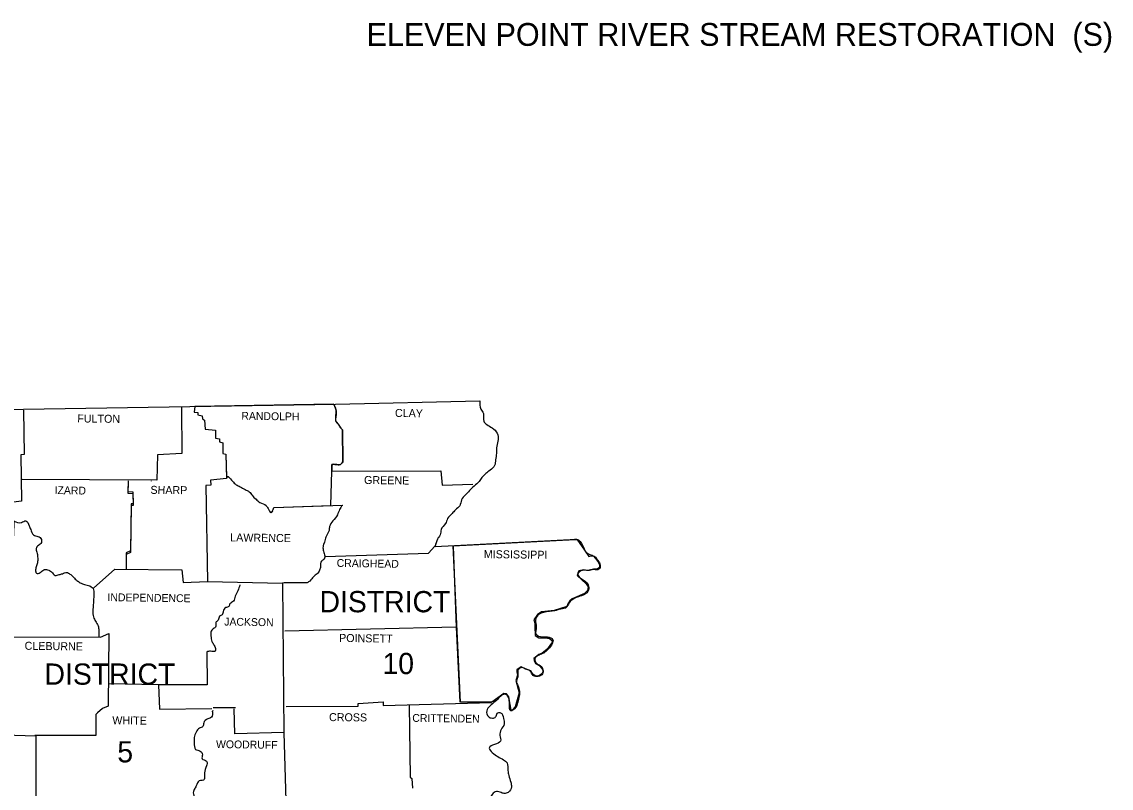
# Model space of a CAD drawing. Extents: x -549 to 3324, y -742 to 2142.
# Drawn here: x 2752 to 3324, y 1662 to 2065 of the extents above; entities that cross this region are included whole.
import ezdxf

# ---------------------------------------------------------------- set-up
doc = ezdxf.new("R2010")
doc.units = 0
for name, color, linetype in [('1', 7, 'Continuous'), ('2', 7, 'Continuous'), ('3', 7, 'Continuous'), ('R_Border', 7, 'Continuous'), ('S_MISC_BOUNDARY', 7, 'Continuous')]:
    doc.layers.add(name, color=color, linetype=linetype)

msp = doc.modelspace()

# ---------------------------------------------------------------- linework, layer by layer
at = {"layer": '1'}
for p, q in [((2915.77, 1863.94), (2842.91, 1862.81)), ((2920.62, 1833.62), (2920.52, 1850.55)), ((2914.85, 1832.35), (2914.85, 1828.73)), ((2914.85, 1828.73), (2914.85, 1832.35)), ((2914.33, 1810.8), (2914.85, 1828.73)), ((2859.45, 1825.76), (2860.55, 1825.8)), ((2884.42, 1809.75), (2914.33, 1810.8)), ((2914.16, 1810.72), (2914.34, 1810.9)), ((2882.86, 1807.1), (2883.8, 1808.03)), ((2969.15, 1789.3), (2970.32, 1792.92)), ((2969.44, 1790.48), (2970.62, 1793.31)), ((2978.62, 1789.66), (3042.98, 1792.83)), ((3042.98, 1792.83), (3043.54, 1792.85)), ((3043.54, 1792.85), (3043.99, 1792.54)), ((3043.99, 1792.54), (3045.23, 1790.75)), ((2982.43, 1707.4), (2978.62, 1789.66)), ((3045.23, 1790.75), (3047.58, 1787.37)), ((3047.58, 1787.37), (3049.93, 1783.98)), ((3049.93, 1783.98), (3051.1, 1784.31)), ((3051.1, 1784.31), (3052.3, 1784.1)), ((3052.3, 1784.1), (3053.39, 1783)), ((3053.39, 1783), (3054.61, 1781.37)), ((3054.61, 1781.37), (3055.54, 1779.56)), ((3044.31, 1775.81), (3043.85, 1774.02)), ((3044.71, 1776.36), (3044.31, 1775.81)), ((3047.22, 1776.92), (3044.71, 1776.36)), ((3049.3, 1776.68), (3047.22, 1776.92)), ((3052.45, 1777.3), (3049.3, 1776.68)), ((3054.34, 1777.33), (3052.45, 1777.3)), ((3055.55, 1778.19), (3054.34, 1777.33)), ((3055.54, 1779.56), (3055.55, 1778.19)), ((3043.85, 1774.02), (3048.55, 1769.65)), ((3048.55, 1769.65), (3049.63, 1768.04)), ((3047.61, 1764.55), (3041.23, 1761.72)), ((3049.21, 1766.16), (3047.61, 1764.55)), ((3049.63, 1768.04), (3049.21, 1766.16)), ((3038.33, 1757.73), (3031.69, 1755.63)), ((3038.82, 1759.16), (3038.33, 1757.73)), ((3039.97, 1760.65), (3038.82, 1759.16)), ((3041.23, 1761.72), (3039.97, 1760.65)), ((3022.89, 1753.52), (3020.94, 1750.76)), ((3025.12, 1754.93), (3022.89, 1753.52)), ((3031.69, 1755.63), (3025.12, 1754.93)), ((3020.94, 1750.76), (3021.55, 1748.97)), ((3021.55, 1748.97), (3021.55, 1747.09)), ((3021.55, 1747.09), (3021.73, 1742.42)), ((3021.73, 1742.42), (3023.7, 1741.24)), ((3023.7, 1741.24), (3025.99, 1741.17)), ((3025.99, 1741.17), (3028.28, 1741.1)), ((3028.28, 1741.1), (3029.12, 1741.07)), ((3029.12, 1741.07), (3030.19, 1740.26)), ((3028.03, 1735.21), (3025.4, 1733.21)), ((3030.84, 1739.21), (3028.03, 1735.21)), ((3030.19, 1740.26), (3030.84, 1739.21)), ((3023.67, 1732.48), (3021.04, 1730.35)), ((3021.04, 1730.35), (3021.13, 1729.35)), ((3021.13, 1729.35), (3021.94, 1727.82)), ((3025.4, 1733.21), (3023.67, 1732.48)), ((3014.34, 1725.93), (3012.02, 1724.44)), ((3012.02, 1724.44), (3012.13, 1723.3)), ((3012.13, 1723.3), (3012.47, 1721.63)), ((3016.57, 1725.02), (3014.34, 1725.93)), ((3019.46, 1723.84), (3016.57, 1725.02)), ((3020.41, 1722.09), (3019.46, 1723.84)), ((3021.94, 1727.82), (3023.87, 1726.75)), ((3023.87, 1726.75), (3025.35, 1724.96)), ((3025.86, 1723.55), (3025.28, 1722.29)), ((3025.35, 1724.96), (3025.86, 1723.55)), ((3012.47, 1721.63), (3011.49, 1718.8)), ((3011.49, 1718.8), (3013.22, 1712.29)), ((3022.15, 1721.11), (3020.41, 1722.09)), ((3023.55, 1721.16), (3022.15, 1721.11)), ((3025.28, 1722.29), (3023.55, 1721.16)), ((3005.26, 1711.99), (2998.98, 1707.52)), ((3006.68, 1711.89), (3005.26, 1711.99)), ((3007.96, 1710.3), (3006.68, 1711.89)), ((3013.22, 1712.29), (3011.16, 1704.98)), ((2998.98, 1707.52), (2982.43, 1707.4)), ((3009.18, 1703.2), (3007.96, 1710.3)), ((2852.52, 1704.57), (2864.17, 1704.57)), ((3009.73, 1703.39), (3009.18, 1703.2)), ((3011.16, 1704.98), (3009.73, 1703.39))]:
    msp.add_line(p, q, dxfattribs=at)
for points in [[(2455.88, 1861.21), (2614.09, 1861.12), (2752.92, 1861.41), (2916.71, 1863.95), (2992.63, 1865.72)], [(2752.92, 1860.82), (2753.12, 1837.54), (2751.45, 1837.44), (2751.75, 1813.08), (2744.9, 1812.1), (2745.49, 1805.54), (2747.83, 1802.51), (2747.64, 1794.78), (2734.33, 1794.29), (2733.84, 1782.36), (2721.71, 1781.96), (2721.12, 1767.48), (2721.81, 1766.31), (2722.1, 1743.22), (2743.04, 1741.85), (2742.75, 1690.29), (2759.38, 1689.8), (2759.38, 1637.36), (2746.27, 1636.38), (2745.29, 1624.83), (2723.28, 1624.73)], [(2835.79, 1862.29), (2835.99, 1838.03), (2823.27, 1837.34), (2822.88, 1824.04), (2752.14, 1824.43)], [(2842.91, 1862.81), (2842.54, 1859.84), (2844.5, 1859.55), (2844.4, 1858.38), (2846.65, 1857.89), (2846.85, 1856.32), (2847.93, 1855.64), (2848.22, 1850.94), (2853.8, 1850.35), (2853.8, 1846.15), (2855.85, 1845.85), (2855.85, 1844.19), (2857.61, 1843.7), (2857.51, 1838.03), (2859.08, 1837.73), (2859.47, 1824.92), (2851.15, 1824.13), (2851.25, 1821.39), (2848.71, 1821.3), (2849.59, 1770.81), (2889.02, 1769.93), (2889.7, 1691.46), (2863.97, 1690.78), (2863.48, 1703.98)], [(2842.91, 1862.81), (2842.54, 1859.84), (2844.5, 1859.55), (2844.4, 1858.38), (2846.65, 1857.89), (2846.85, 1856.32), (2847.93, 1855.64), (2848.22, 1850.94), (2853.8, 1850.35), (2853.8, 1846.15), (2855.85, 1845.85), (2855.85, 1844.19), (2857.61, 1843.7), (2857.51, 1838.03), (2859.08, 1837.73), (2859.45, 1825.76)], [(2920.52, 1850.55), (2920.62, 1833.62)], [(2914.33, 1810.8), (2914.85, 1828.73), (2914.85, 1828.73), (2972.09, 1829.03), (2972.87, 1821.39), (2989.01, 1821.98)], [(2807.81, 1823.74), (2807.62, 1818.07), (2810.35, 1817.87), (2810.45, 1811.61), (2809.47, 1811.61), (2809.08, 1786.95), (2806.83, 1785.98), (2806.83, 1777.76)], [(2807.81, 1822.86), (2807.62, 1817.19), (2810.35, 1816.99), (2810.45, 1810.73), (2809.47, 1810.73), (2809.08, 1786.07), (2806.83, 1785.09), (2806.83, 1776.88)], [(2820.04, 1823.55), (2820.14, 1823.64)], [(2884.42, 1809.75), (2920.72, 1811.02)], [(2969.15, 1789.3), (3043.41, 1793.12)], [(2911.42, 1783.92), (2965.73, 1785.68), (2968.95, 1789.4)], [(2978.54, 1789.2), (2980.21, 1746.84), (2982.16, 1707.41)], [(2789.61, 1767.29), (2800.77, 1777.37), (2835.99, 1776.88), (2836.67, 1770.32), (2849.49, 1770.81)], [(2901.84, 1770.13), (2889.9, 1770.13), (2889.02, 1769.93)], [(2980.21, 1746.84), (2890.1, 1744.78)], [(2743.04, 1741.85), (2793.33, 1741.56), (2797.64, 1743.61), (2797.34, 1705.35), (2794.41, 1704.08), (2791.77, 1701.83), (2790.88, 1700.95), (2790.79, 1689.99), (2758.79, 1689.99)], [(2849.1, 1733.83), (2849.3, 1716.61), (2823.86, 1716.51), (2797.73, 1717)], [(2823.86, 1716.51), (2824.25, 1703.69), (2851.74, 1704.18)], [(2890.88, 1705.16), (2928.64, 1705.35), (2928.74, 1706.72), (2941.85, 1707.7), (2941.85, 1705.65), (2998.8, 1707.21)], [(2852.52, 1702.91), (2852.04, 1702.81)], [(2955.55, 1705.65), (2956.04, 1667.98), (2956.92, 1667.39), (2957.21, 1662.3)], [(2889.7, 1691.46), (2891.17, 1637.84), (2867.89, 1637.75), (2867.79, 1635.59), (2861.04, 1635.2), (2860.45, 1624.05), (2852.23, 1624.05)]]:
    msp.add_lwpolyline(points, dxfattribs=at)
for points in [[(2915.76, 1863.94), (2917.1, 1860.24), (2917, 1857.59), (2917, 1855.15), (2918.27, 1853.49), (2919.55, 1851.43), (2920.52, 1850.55)], [(2920.52, 1850.55), (2920.25, 1850.75), (2920, 1850.96), (2919.76, 1851.18), (2919.55, 1851.43), (2919.37, 1851.68), (2919.2, 1851.93), (2918.89, 1852.45), (2918.59, 1852.98), (2918.27, 1853.49), (2918.11, 1853.69), (2917.93, 1853.89), (2917.54, 1854.27), (2917.2, 1854.68), (2917, 1855.15), (2916.99, 1855.22), (2916.98, 1855.3), (2916.96, 1855.45), (2916.93, 1855.76), (2916.94, 1856.37), (2916.99, 1857.29), (2917, 1857.59), (2917.02, 1858.26), (2917.06, 1858.92), (2917.08, 1859.58), (2917.1, 1860.24), (2917.09, 1860.74), (2917.04, 1861.24), (2916.81, 1862.25), (2916.11, 1863.58), (2915.77, 1863.94)], [(2992.63, 1865.72), (2993.12, 1861.41), (2994.49, 1859.16), (2994.69, 1855.05), (2996.35, 1853.29), (2999.19, 1851.53), (3001.73, 1848.69), (3002.32, 1845.36), (3001.54, 1841.94), (3001.34, 1838.12), (3000.95, 1834.8), (3000.36, 1831.76), (2998.01, 1829.32), (2995.76, 1827.56), (2993.71, 1825.5), (2992.24, 1823.35), (2989.7, 1821), (2987.15, 1818.56), (2985.1, 1816.4), (2983.04, 1813.66), (2982.07, 1810.63), (2979.82, 1808.48), (2978.05, 1806.52), (2975.71, 1803.88), (2974.53, 1801.24), (2972.28, 1798.21), (2971.79, 1795.27), (2970.32, 1792.92), (2970.23, 1792.53)], [(2920.62, 1833.62), (2919.35, 1832.35), (2916.9, 1832.35), (2914.85, 1832.35)], [(2914.85, 1832.35), (2916.9, 1832.35), (2919.35, 1832.35), (2920.62, 1833.62)], [(2860.55, 1825.8), (2862.7, 1823.55), (2864.56, 1821.69), (2866.71, 1820.61), (2869.26, 1819.14), (2871.51, 1817.97), (2872.97, 1816.11), (2875.03, 1814.06), (2877.08, 1812.39), (2880.31, 1810.83), (2881.39, 1809.16), (2882.85, 1807.11), (2884.42, 1809.75)], [(2860.55, 1825.8), (2862.7, 1823.55), (2864.56, 1821.69), (2866.71, 1820.61), (2869.26, 1819.14), (2871.51, 1817.97), (2872.97, 1816.11), (2875.03, 1814.06), (2877.08, 1812.39), (2880.31, 1810.83), (2881.39, 1809.16), (2882.85, 1807.11), (2884.42, 1809.75)], [(2920.43, 1810.92), (2918.96, 1808.58), (2917.78, 1805.84), (2915.44, 1802.71), (2913.67, 1799.67), (2913.38, 1797.62), (2912.01, 1794.88), (2911.23, 1792.14), (2910.35, 1789.79), (2910.35, 1787.35), (2911.03, 1784.9), (2910.84, 1782.65), (2909.37, 1781.57), (2908.98, 1778.74), (2908.39, 1776.78), (2907.12, 1774.82), (2905.26, 1773.35), (2903.3, 1771.1), (2901.84, 1770.13)], [(2747.83, 1802.51), (2751.75, 1801.83), (2754.1, 1802.71), (2755.76, 1800.16), (2756.64, 1798.21), (2758.11, 1795.37), (2760.46, 1794.49), (2762.22, 1792.92), (2762.22, 1791.26), (2760.65, 1789.69), (2759.48, 1788.13), (2759.87, 1786.27), (2760.26, 1783.72), (2760.26, 1781.28), (2759.67, 1779.03), (2759.18, 1776.97), (2759.67, 1775.21), (2761.53, 1775.51), (2763.49, 1776.97), (2765.54, 1776.97), (2767.5, 1775.9), (2769.56, 1774.04), (2771.61, 1774.43), (2773.27, 1774.92), (2775.62, 1775.6), (2777.28, 1774.72), (2778.75, 1773.55), (2780.51, 1771.69), (2782.18, 1770.52), (2784.33, 1769.44), (2786.97, 1768.76), (2789.42, 1767.09), (2789.81, 1764.25), (2789.71, 1761.81), (2789.51, 1758.78), (2789.32, 1755.45), (2789.61, 1752.22), (2790.69, 1750.07), (2792.06, 1747.52), (2792.45, 1745.18), (2792.35, 1741.46)], [(3042.34, 1793.02), (3043.41, 1793.12), (3046.74, 1789.6), (3048.21, 1786.66), (3050.36, 1785), (3052.8, 1784.12), (3054.66, 1781.87), (3055.94, 1779.42), (3055.25, 1777.27), (3052.51, 1777.07), (3049.48, 1776.58), (3046.54, 1776.68), (3044.19, 1774.72), (3046.35, 1772.08), (3049.18, 1769.64), (3049.97, 1766.99), (3048.4, 1764.45), (3045.27, 1763.08), (3042.24, 1761.91), (3039.5, 1759.56), (3038.23, 1757.31), (3035.19, 1756.33), (3032.06, 1755.45), (3029.32, 1755.16), (3026.19, 1754.57), (3023.16, 1753.1), (3021.89, 1750.56), (3022.28, 1746.94), (3022.18, 1743.12), (3025.41, 1741.85), (3028.25, 1741.75), (3030.99, 1740.28), (3030.69, 1738.13), (3028.64, 1735.39), (3026.19, 1733.24), (3023.75, 1732.16), (3021.5, 1730.11), (3022.28, 1728.05), (3024.33, 1726.68), (3025.8, 1724.43), (3025.6, 1722.38), (3023.26, 1720.91), (3020.71, 1721.5), (3018.85, 1723.94), (3016.7, 1724.73), (3014.84, 1725.61), (3012.69, 1724.34), (3012.69, 1721.5), (3011.91, 1718.47), (3012.59, 1716.21), (3013.47, 1713.08), (3013.37, 1710.74), (3012.59, 1707.41), (3010.93, 1703.98), (3008.97, 1702.91), (3008.19, 1706.63), (3007.8, 1709.66), (3006.62, 1711.42), (3005.06, 1711.52), (3003, 1710.05), (3000.75, 1707.8), (2997.92, 1705.35), (2996.25, 1702.91), (2997.13, 1699.88), (2999.29, 1699.09), (3000.95, 1699.68), (3001.83, 1701.64), (3003.49, 1701.93), (3005.06, 1698.9)], [(2866.61, 1769.05), (2865.44, 1766.02), (2864.07, 1763.08), (2863.19, 1760.54), (2861.33, 1759.07), (2860.74, 1757.7), (2859.08, 1757.11), (2857.81, 1755.16), (2857.22, 1753.39), (2855.85, 1752.61), (2855.17, 1750.46), (2853.89, 1749.29), (2853.99, 1747.33), (2852.52, 1745.96), (2851.35, 1744.39), (2851.35, 1742.24), (2851.84, 1739.4), (2852.82, 1737.74), (2853.7, 1735.59), (2853.6, 1734.22), (2851.15, 1734.22), (2849.1, 1733.83)], [(2852.04, 1702.81), (2851.55, 1699.58), (2849.69, 1698.7), (2847.53, 1696.55), (2847.05, 1694.59), (2845.28, 1693.81), (2843.62, 1691.75), (2842.54, 1688.92), (2842.54, 1685.98), (2843.23, 1682.66), (2845.68, 1681.77), (2846.85, 1679.82), (2846.65, 1677.76), (2849, 1676.39), (2849.39, 1675.22), (2849, 1673.95), (2847.93, 1670.33), (2848.02, 1667.88), (2847.83, 1666.81), (2845.19, 1666.12), (2843.62, 1663.48), (2842.54, 1661.62), (2842.15, 1659.17), (2842.45, 1657.41), (2841.66, 1656.04), (2841.37, 1653.99), (2840.39, 1652.23), (2839.51, 1650.56), (2840.49, 1648.61), (2840.2, 1647.24), (2839.61, 1645.08), (2840.1, 1644.4)], [(3005.06, 1698.9), (3005.45, 1696.06), (3003.79, 1693.03), (3003.2, 1689.99), (3003.49, 1686.96), (3000.36, 1685.3), (2997.62, 1683.34), (2999.19, 1680.99), (3002.12, 1678.84), (3005.06, 1677.18), (3006.92, 1675.51), (3007.41, 1671.5), (3007.9, 1668.96), (3008.87, 1665.44), (3009.27, 1662.99), (3007.5, 1660.05), (3005.45, 1659.47), (3003.3, 1660.15), (3000.75, 1660.35), (2998.7, 1658.39), (2997.23, 1655.65), (2995.76, 1652.91), (2994.69, 1650.56), (2993.61, 1648.02), (2991.46, 1645.08), (2988.82, 1644.6), (2985.69, 1643.81), (2983.83, 1641.66), (2984.12, 1638.04), (2985.88, 1635.59), (2987.25, 1632.56), (2988.23, 1629.92), (2987.74, 1626.59), (2986.37, 1624.15), (2984.61, 1622.68), (2983.83, 1619.55), (2982.55, 1617.2), (2981.38, 1616.42), (2979.03, 1616.61), (2976.49, 1617.1), (2974.34, 1616.91), (2972.28, 1615.83), (2970.23, 1616.52), (2968.07, 1618.86), (2966.31, 1620.62), (2964.36, 1621.31), (2962.3, 1620.23), (2961.91, 1617), (2962.89, 1613.68), (2963.77, 1609.18), (2962.89, 1606.44), (2962.6, 1601.94)]]:
    msp.add_spline(points, degree=3, dxfattribs=at)
at = {"layer": 'S_MISC_BOUNDARY'}
msp.add_line((2860.55, 1825.8), (2859.45, 1825.76), dxfattribs=at)

# ---------------------------------------------------------------- texts
at = {"layer": '2'}
for s, height, rotation, p in [('CLAY', 4.206, 359.2258, (2948.02, 1857.3)), ('FULTON', 4.206, 359.4996, (2781.1, 1854.37)), ('RANDOLPH', 4.109, 359.2583, (2867.3, 1855.83)), ('GREENE', 4.207, 359.2361, (2931.78, 1822.08)), ('IZARD', 4.108, 358.9258, (2769.16, 1816.8)), ('SHARP', 4.206, 359.3905, (2819.55, 1816.89)), ('LAWRENCE', 4.207, 359.2678, (2861.45, 1791.91)), ('MISSISSIPPI', 4.2062, 359.3097, (2994.69, 1783.14)), ('CRAIGHEAD', 4.109, 359.1159, (2917.39, 1778.54)), ('INDEPENDENCE', 4.1081, 359.2187, (2796.95, 1760.54)), ('JACKSON', 4.108, 359.1352, (2858.3, 1747.72)), ('POINSETT', 4.206, 359.1987, (2918.66, 1739.11)), ('CLEBURNE', 4.206, 359.2535, (2753.41, 1735)), ('CROSS', 4.206, 359.3839, (2913.38, 1697.53)), ('CRITTENDEN', 4.109, 359.213, (2957.12, 1697.14)), ('WHITE', 4.207, 359.3139, (2799.49, 1695.86)), ('WOODRUFF', 4.108, 359.2748, (2853.99, 1683.34))]:
    msp.add_text(s, height=height, rotation=rotation, dxfattribs=at).set_placement(p)
at = {"layer": '3'}
for s, height, p in [('DISTRICT', 11.154, (2908.39, 1754.67)), ('10', 11.154, (2941.46, 1722.18)), ('DISTRICT', 11.154, (2763.88, 1716.61)), ('5', 11.15, (2802.14, 1675.81))]:
    msp.add_text(s, height=height, dxfattribs=at).set_placement(p)
at = {"layer": 'R_Border'}
msp.add_text('ELEVEN POINT RIVER STREAM RESTORATION  (S)', height=12, dxfattribs=at).set_placement((2933.1, 2052.22))

doc.saveas('drawing.dxf')
